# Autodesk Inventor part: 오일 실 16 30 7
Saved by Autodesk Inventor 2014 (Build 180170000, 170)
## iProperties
Created: 2026-09
Part Number: 오일 실 16 30 7
Material: 일반
Document SubType Name: Modeling
Designer: dg
Density: 1 g/cm^3
Appearance: 기본값
Author: dg
Author: jhkim
Description: 오일-실
Creation Date: 2026-08-26
Sending System: Autodesk Inventor 2027
Preprocessor: ST-DEVELOPER v20.1
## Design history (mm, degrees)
node "오일 실 16 30 71"
body "Solid1"
node "기준1"
